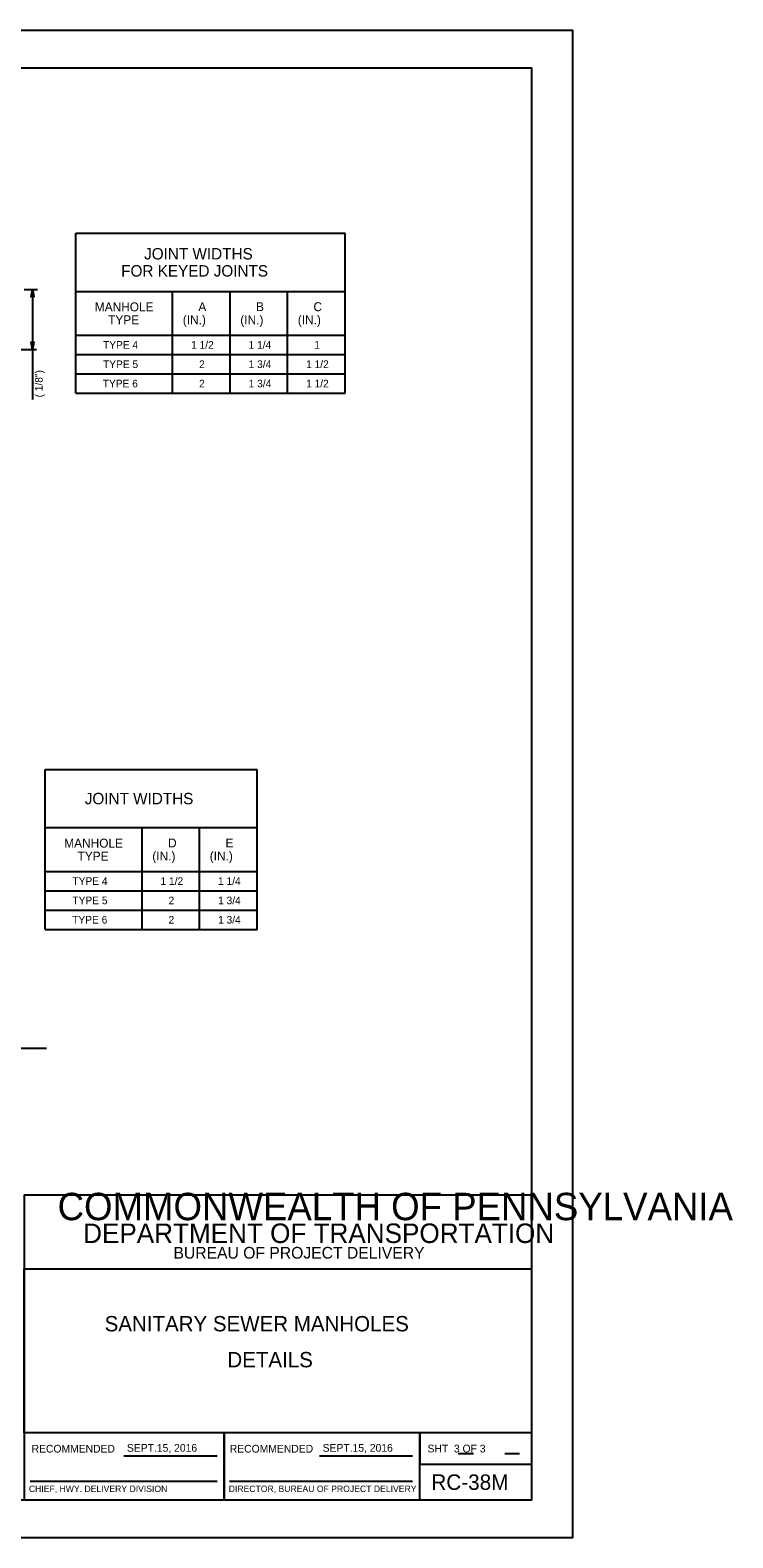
# Model space of a CAD drawing. Extents: x 2106427 to 2114911, y 988717 to 990787.
# Drawn here: x 2114003 to 2114911, y 988839 to 990787 of the extents above; entities that cross this region are included whole.
import ezdxf

# ---------------------------------------------------------------- set-up
doc = ezdxf.new("R2010")
doc.units = 0
for name, color, linetype in [('1', 7, 'Continuous'), ('2', 7, 'Continuous'), ('3', 7, 'Continuous'), ('PLT-BNDY', 7, 'Continuous')]:
    doc.layers.add(name, color=color, linetype=linetype)

msp = doc.modelspace()

# ---------------------------------------------------------------- linework, layer by layer
at = {"layer": '1'}
for p, q in [((2114062.2, 990318.1), (2114062.2, 990524.7)), ((2114062.2, 990524.7), (2114410, 990524.7)), ((2114410, 990318.1), (2114410, 990524.7)), ((2113995.4, 990452.3), (2114012.8, 990452.3)), ((2114006.2, 990452.3), (2114006.2, 990309.9)), ((2114062.2, 990449.7), (2114410, 990449.7)), ((2114187.2, 990318.1), (2114187.2, 990449.7)), ((2114261.4, 990318.1), (2114261.4, 990449.7)), ((2114335.7, 990318.1), (2114335.7, 990449.7)), ((2114062.2, 990393.1), (2114410, 990393.1)), ((2113884.5, 990374.4), (2114011.3, 990374.4)), ((2114062.2, 990368.1), (2114410, 990368.1)), ((2114062.2, 990343.1), (2114410, 990343.1)), ((2114062.2, 990318.1), (2114410, 990318.1)), ((2114022.7, 989624.9), (2114022.7, 989831.6)), ((2114022.7, 989831.6), (2114296.3, 989831.6)), ((2114296.3, 989624.9), (2114296.3, 989831.6)), ((2114022.7, 989756.6), (2114296.3, 989756.6)), ((2114147.7, 989624.9), (2114147.7, 989756.6)), ((2114222, 989624.9), (2114222, 989756.6)), ((2114022.7, 989699.9), (2114296.3, 989699.9)), ((2114022.7, 989674.9), (2114296.3, 989674.9)), ((2114022.7, 989649.9), (2114296.3, 989649.9)), ((2114022.7, 989624.9), (2114296.3, 989624.9)), ((2113206, 989471.6), (2114024.1, 989471.6)), ((2114124.4, 988944.7), (2114244.8, 988944.7)), ((2114377, 988944.7), (2114497.4, 988944.7)), ((2114556.1, 988947.4), (2114576.2, 988947.4)), ((2114616.5, 988947.4), (2114635.3, 988947.4)), ((2114003.3, 988911.7), (2114244.8, 988911.7)), ((2114260.9, 988911.7), (2114497.4, 988911.7))]:
    msp.add_line(p, q, dxfattribs=at)
for points in [[(2114651.6, 988887.7), (2114651.6, 990738.1), (2112072.8, 990738.1), (2112072.8, 988887.7), (2114651.6, 988887.7), (2114651.6, 988974.2), (2113995.4, 988974.2), (2113995.4, 989186.4), (2114651.6, 989186.4), (2114651.6, 989281.4), (2113995.4, 989281.4), (2113995.4, 988887.7), (2114253.9, 988887.7), (2114253.9, 988974.2), (2114253.9, 988887.7), (2114506.6, 988887.7), (2114506.6, 988974.2), (2114506.6, 988933.8), (2114651.6, 988933.8)], [(2114006.2, 990452.3), (2114008, 990442.5), (2114007.7, 990442.9), (2114007.5, 990443.3), (2114007.2, 990443.5), (2114006.8, 990443.7), (2114006.5, 990443.7), (2114006.2, 990443.8), (2114005.8, 990443.7), (2114005.5, 990443.7), (2114005.2, 990443.5), (2114004.9, 990443.3), (2114004.6, 990442.9), (2114004.3, 990442.5), (2114006.2, 990452.3), (2114004.6, 990442.9), (2114004.9, 990443.3), (2114006.2, 990452.3), (2114005.2, 990443.5), (2114005.5, 990443.7), (2114006.2, 990452.3), (2114005.8, 990443.7), (2114006.2, 990443.8), (2114006.2, 990452.3), (2114006.5, 990443.7), (2114006.8, 990443.7), (2114006.2, 990452.3), (2114007.2, 990443.5), (2114007.5, 990443.3), (2114006.2, 990452.3), (2114007.7, 990442.9)], [(2114006.2, 990374.4), (2114004.3, 990384.2), (2114004.6, 990383.8), (2114004.9, 990383.4), (2114005.2, 990383.2), (2114005.5, 990383), (2114005.8, 990383), (2114006.2, 990382.9), (2114006.5, 990383), (2114006.8, 990383), (2114007.2, 990383.2), (2114007.5, 990383.4), (2114007.7, 990383.8), (2114008, 990384.2), (2114006.2, 990374.4), (2114007.7, 990383.8), (2114007.5, 990383.4), (2114006.2, 990374.4), (2114007.2, 990383.2), (2114006.8, 990383), (2114006.2, 990374.4), (2114006.5, 990383), (2114006.2, 990382.9), (2114006.2, 990374.4), (2114005.8, 990383), (2114005.5, 990383), (2114006.2, 990374.4), (2114005.2, 990383.2), (2114004.9, 990383.4), (2114006.2, 990374.4), (2114004.6, 990383.8)]]:
    msp.add_lwpolyline(points, dxfattribs=at)
at = {"layer": 'PLT-BNDY'}
msp.add_lwpolyline([(2111944.9, 990787.3), (2114704.1, 990787.3), (2114704.1, 988838.5), (2111944.9, 988838.5)], close=True, dxfattribs=at)

# ---------------------------------------------------------------- texts
at = {"layer": '1'}
msp.add_text('SANITARY SEWER MANHOLES', height=19.816, dxfattribs=at).set_placement((2114099.4, 989105.4))
at = {"layer": '2'}
msp.add_text('DETAILS', height=19.82, dxfattribs=at).set_placement((2114258, 989058.9))
at = {"layer": '3'}
for s, height, p in [('JOINT WIDTHS', 14.764, (2114150.4, 990490.9)), ('FOR KEYED JOINTS', 14.764, (2114120.8, 990468.8)), ('MANHOLE', 11.48, (2114086.7, 990423.9)), ('A', 11.5, (2114220.5, 990424.1)), ('B', 11.5, (2114295, 990424.1)), ('C', 11.5, (2114369.3, 990424.1)), ('TYPE', 11.48, (2114103.9, 990407.1)), ('(IN.)', 11.48, (2114200.4, 990407.2)), ('(IN.)', 11.48, (2114274.7, 990407.2)), ('(IN.)', 11.48, (2114349, 990407.2)), ('TYPE 4', 9.84, (2114097.3, 990375.6)), ('1 1/2', 9.84, (2114211.1, 990375.6)), ('1 1/4', 9.84, (2114285.4, 990375.6)), ('1', 9.84, (2114370.3, 990375.6)), ('TYPE 5', 9.84, (2114097.3, 990350.6)), ('2', 9.84, (2114221.5, 990350.6)), ('1 3/4', 9.84, (2114285.5, 990350.6)), ('1 1/2', 9.84, (2114359.7, 990350.6)), ('TYPE 6', 9.84, (2114097, 990325.6)), ('2', 9.84, (2114221.5, 990325.6)), ('1 3/4', 9.84, (2114285.5, 990325.6)), ('1 1/2', 9.84, (2114359.7, 990325.6)), ('JOINT WIDTHS', 14.764, (2114073.7, 989786.7)), ('MANHOLE', 11.48, (2114047.2, 989730.7)), ('D', 11.5, (2114181.3, 989730.9)), ('E', 11.5, (2114255.6, 989730.9)), ('TYPE', 11.48, (2114064.4, 989713.9)), ('(IN.)', 11.48, (2114161, 989714.1)), ('(IN.)', 11.48, (2114235.2, 989714.1)), ('TYPE 4', 9.84, (2114057.8, 989682.5)), ('1 1/2', 9.84, (2114171.6, 989682.5)), ('1 1/4', 9.84, (2114245.9, 989682.5)), ('TYPE 5', 9.84, (2114057.8, 989657.5)), ('2', 9.84, (2114182, 989657.5)), ('1 3/4', 9.84, (2114246, 989657.5)), ('TYPE 6', 9.84, (2114057.5, 989632.5)), ('2', 9.84, (2114182, 989632.5)), ('1 3/4', 9.84, (2114246, 989632.5)), ('COMMONWEALTH OF PENNSYLVANIA', 35.379, (2114038.6, 989249.1)), ('DEPARTMENT OF TRANSPORTATION', 25.211, (2114071.6, 989219.6)), ('BUREAU OF PROJECT DELIVERY', 15.164, (2114188.3, 989199.4)), ('RECOMMENDED', 10, (2114005, 988948.7)), ('SEPT.15, 2016', 10, (2114128.2, 988949.8)), ('RECOMMENDED', 10, (2114261.1, 988948.7)), ('SEPT.15, 2016', 10, (2114381.1, 988949.8)), ('SHT  3 OF 3', 10, (2114516.6, 988948.9)), ('RC-38M', 20, (2114521.6, 988900.5)), ('CHIEF, HWY. DELIVERY DIVISION', 8.333, (2114001.5, 988897.7)), ('DIRECTOR, BUREAU OF PROJECT DELIVERY', 8.333, (2114259.7, 988897.7))]:
    msp.add_text(s, height=height, dxfattribs=at).set_placement(p)
msp.add_text('( 1/8")', height=9.84, rotation=90, dxfattribs=at).set_placement((2114019.3, 990312.6))

doc.saveas('drawing.dxf')
